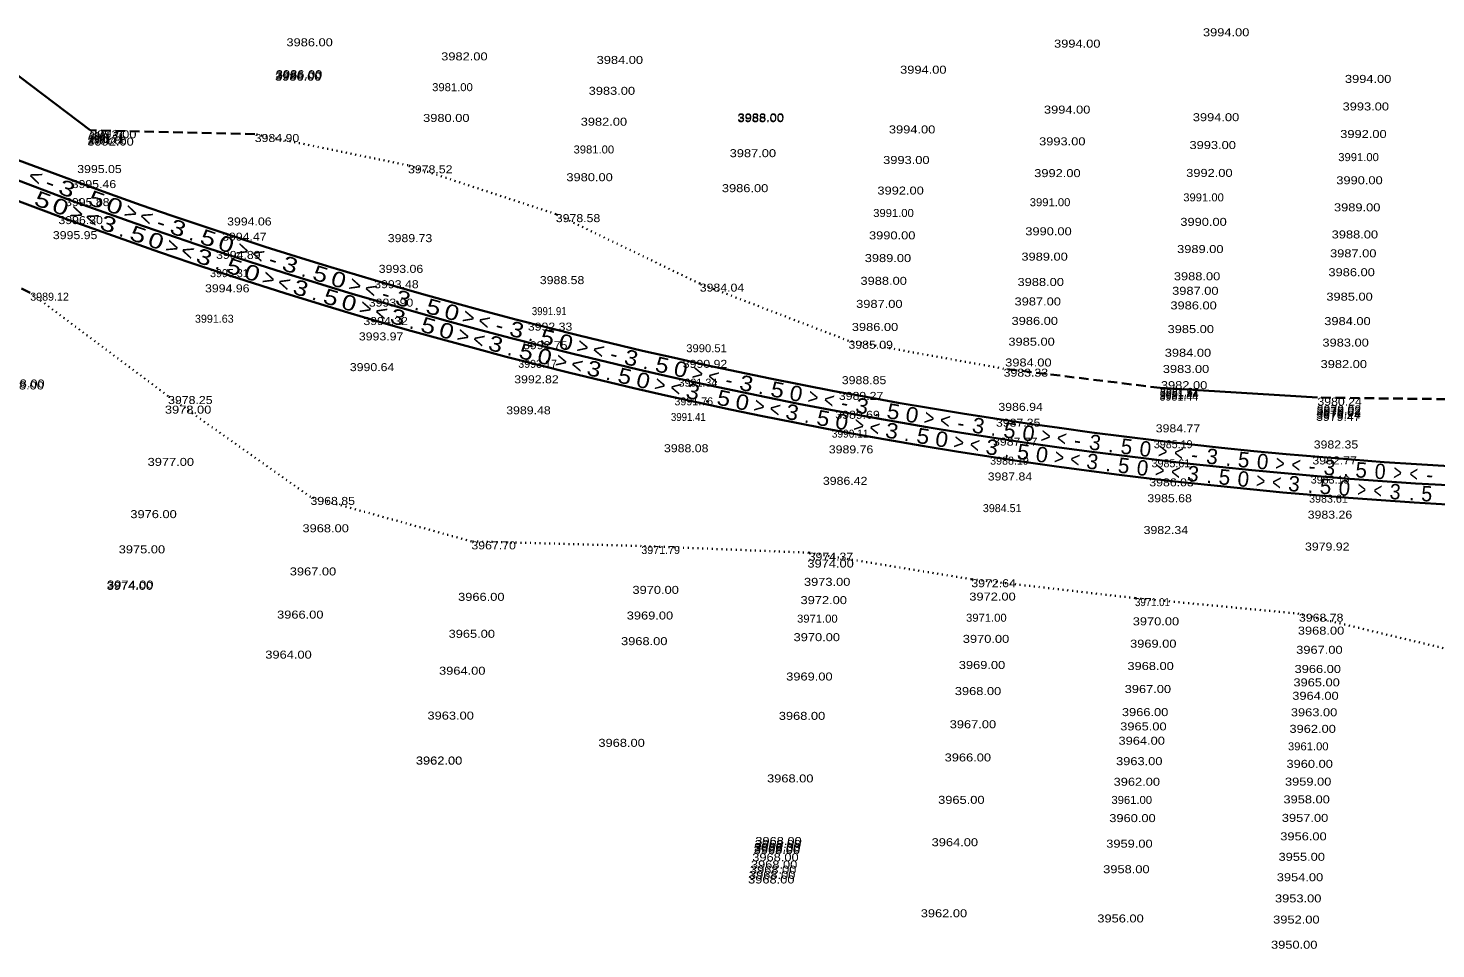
# Model space of a CAD drawing. Extents: x 49942 to 56479, y 47140 to 53283.
# Drawn here: x 51291 to 52171, y 49473 to 50048 of the extents above; entities that cross this region are included whole.
import ezdxf
from ezdxf.enums import TextEntityAlignment as Align

# ---------------------------------------------------------------- set-up
doc = ezdxf.new("R2010")
doc.units = 0
doc.header["$LTSCALE"] = 2
doc.linetypes.add('DOTTED', pattern=[1.5, 0.3, -1.2])
doc.linetypes.add('MEDIUM_DASHED', pattern=[4.5, 3, -1.5])
doc.layers.add('29', color=7, linetype='Continuous')
doc.layers.add('59', color=7, linetype='Continuous', lineweight=35)
doc.layers.add('63', color=7, linetype='Continuous', lineweight=35)

msp = doc.modelspace()

# ---------------------------------------------------------------- linework, layer by layer
at = {"layer": '59'}
for p, q in [((51329.711, 49984.424), (51248.45, 50045.982)), ((52096.806, 49817.413), (51998.49, 49823.498))]:
    msp.add_line(p, q, dxfattribs=at)
at = {"layer": '59', "linetype": 'MEDIUM_DASHED'}
for p, q in [((51432.659, 49982.089), (51329.711, 49984.424)), ((51292.327, 49882.958), (51199.974, 49926.861)), ((51998.49, 49823.498), (51900.7, 49835.484)), ((52195.222, 49816.237), (52096.806, 49817.413))]:
    msp.add_line(p, q, dxfattribs=at)
at = {"layer": '59', "linetype": 'DOTTED'}
for p, q in [((51528.445, 49962.551), (51432.659, 49982.089)), ((51620.827, 49932.041), (51528.445, 49962.551)), ((51710.779, 49888.632), (51620.827, 49932.041)), ((51803.733, 49852.933), (51710.779, 49888.632)), ((51378.49, 49818.374), (51292.327, 49882.958)), ((51900.7, 49835.484), (51803.733, 49852.933)), ((51467.508, 49755.369), (51378.49, 49818.374)), ((51568.059, 49727.587), (51467.508, 49755.369)), ((51674.271, 49724.686), (51568.059, 49727.587)), ((51778.869, 49720.528), (51674.271, 49724.686)), ((51880.529, 49703.937), (51778.869, 49720.528)), ((51982.829, 49692.148), (51880.529, 49703.937)), ((52085.276, 49682.412), (51982.829, 49692.148)), ((52187.039, 49658.165), (52085.276, 49682.412))]:
    msp.add_line(p, q, dxfattribs=at)
at = {"layer": '63'}
for radius in [2975.18, 2987.18, 2987.18, 2999.18]:
    msp.add_arc((52346.841, 52745.042), radius, 246.32672, 271.49967, dxfattribs=at)

# ---------------------------------------------------------------- texts
at = {"layer": '29'}
for s, width, p in [('3994.00', 1.2, (52025.278, 50043.161)), ('3986.00', 1.2, (51452.451, 50036.909)), ('3994.00', 1.2, (51932.224, 50036.07)), ('3982.00', 1.2, (51549.192, 50028.091)), ('3984.00', 1.2, (51646.339, 50025.89)), ('3986.00', 1.2, (51445.341, 50015.42)), ('3986.00', 1.2, (51445.601, 50016.203)), ('3986.00', 1.2, (51445.86, 50016.986)), ('3994.00', 1.2, (51836.006, 50019.792)), ('3994.00', 1.2, (52114.025, 50014.035)), ('3981.00', 1.05, (51543.539, 50008.868)), ('3983.00', 1.2, (51641.358, 50006.591)), ('3994.00', 1.2, (51925.905, 49994.86)), ('3993.00', 1.2, (52112.555, 49996.82)), ('3980.00', 1.2, (51537.885, 49989.645)), ('3982.00', 1.2, (51636.377, 49987.293)), ('3988.00', 1.2, (51734.349, 49989.482)), ('3988.00', 1.2, (51734.387, 49989.651)), ('3988.00', 1.2, (51734.425, 49989.82)), ('3988.00', 1.2, (51734.449, 49989.93)), ('3988.00', 1.2, (51734.473, 49990.039)), ('3994.00', 1.2, (52018.951, 49990.102)), ('3991.71', 0.9, (51328.969, 49977.41)), ('3991.71', 0.9, (51329.315, 49978.348)), ('3992.00', 1.2, (51329.711, 49979.424)), ('3984.90', 1.15, (51432.659, 49977.089)), ('3994.00', 1.2, (51828.998, 49982.471)), ('3992.00', 1.2, (52111.085, 49979.605)), ('3992.00', 1.2, (51328.029, 49974.858)), ('3991.71', 0.9, (51328.623, 49976.472)), ('3981.00', 1.05, (51631.902, 49969.953)), ('3993.00', 1.2, (51922.862, 49975.016)), ('3993.00', 1.2, (52016.876, 49972.7)), ('3987.00', 1.2, (51729.482, 49967.623)), ('3993.00', 1.2, (51825.411, 49963.369)), ('3991.00', 1.05, (52109.851, 49965.153)), ('3995.05', 1.15, (51321.709, 49957.705)), ('3978.52', 1.15, (51528.445, 49957.551)), ('3980.00', 1.2, (51627.427, 49952.613)), ('3992.00', 1.2, (51919.819, 49955.172)), ('3992.00', 1.2, (52014.801, 49955.297)), ('3990.00', 1.2, (52108.617, 49950.701)), ('3995.46', 1.15, (51318.252, 49948.322)), ('3986.00', 1.2, (51724.615, 49945.765)), ('3992.00', 1.2, (51821.824, 49944.268)), ('3995.88', 1.15, (51314.103, 49937.062)), ('3991.00', 1.05, (51917.033, 49936.999)), ('3991.00', 1.05, (52012.979, 49940.012)), ('3989.00', 1.2, (52107.171, 49933.776)), ('3996.30', 1.15, (51309.954, 49925.801)), ('3994.06', 1.15, (51415.408, 49924.953)), ('3978.58', 1.15, (51620.827, 49927.041)), ('3991.00', 1.05, (51819.196, 49930.275)), ('3990.00', 1.2, (52011.156, 49924.726)), ('3995.95', 1.15, (51306.497, 49916.418)), ('3994.47', 1.15, (51412.267, 49915.459)), ('3990.00', 1.2, (51816.568, 49916.282)), ('3990.00', 1.2, (51914.246, 49918.826)), ('3988.00', 1.2, (52105.726, 49916.851)), ('3989.73', 1.15, (51515.795, 49914.542)), ('3989.00', 1.2, (52009.129, 49907.723)), ('3994.89', 1.15, (51408.498, 49904.066)), ('3989.00', 1.2, (51813.901, 49902.079)), ('3989.00', 1.2, (51911.818, 49902.991)), ('3987.00', 1.2, (52104.718, 49905.051)), ('3993.06', 1.15, (51510.152, 49895.355)), ('3988.00', 1.2, (52007.101, 49890.719)), ('3986.00', 1.2, (52103.71, 49893.252)), ('3994.96', 1.15, (51401.587, 49883.18)), ('3993.48', 1.15, (51507.33, 49885.761)), ('3988.58', 1.15, (51610.831, 49888.31)), ('3984.04', 1.15, (51710.779, 49883.632)), ('3988.00', 1.2, (51811.234, 49887.877)), ('3988.00', 1.2, (51909.39, 49887.155)), ('3987.00', 1.2, (52006.018, 49881.636)), ('3993.90', 1.15, (51503.944, 49874.249)), ('3987.00', 1.2, (51808.528, 49873.466)), ('3987.00', 1.2, (51907.525, 49874.993)), ('3986.00', 1.2, (52004.93, 49872.506)), ('3985.00', 1.2, (52102.406, 49877.982)), ('3994.32', 1.15, (51500.558, 49862.736)), ('3991.91', 0.9, (51605.832, 49868.944)), ('3986.00', 1.2, (51905.66, 49862.831)), ('3984.00', 1.2, (52101.102, 49862.713)), ('3992.33', 1.15, (51603.333, 49859.262)), ('3986.00', 1.2, (51805.822, 49859.056)), ('3985.00', 1.2, (52003.167, 49857.719)), ('3993.97', 1.15, (51497.736, 49853.143)), ('3992.75', 1.15, (51600.335, 49847.642)), ('3990.51', 1.05, (51702.344, 49845.751)), ('3985.09', 1.15, (51803.733, 49847.933)), ('3985.00', 1.2, (51903.668, 49849.842)), ('3983.00', 1.2, (52099.955, 49849.287)), ('3990.92', 1.15, (51700.17, 49835.99)), ('3984.00', 1.2, (51901.677, 49836.854)), ('3984.00', 1.2, (52001.404, 49842.932)), ('3982.00', 1.2, (52098.809, 49835.861)), ('3990.64', 1.15, (51492.093, 49833.955)), ('3983.33', 1.15, (51900.7, 49830.484)), ('3983.00', 1.2, (52000.197, 49832.814)), ('3988.00', 1.2, (51271.892, 49822.495)), ('3988.00', 1.2, (51272.345, 49823.726)), ('3992.82', 1.15, (51594.837, 49826.34)), ('3988.85', 1.15, (51799.577, 49825.801)), ('3982.00', 1.2, (51998.99, 49822.689)), ('3978.25', 1.15, (51378.49, 49813.374)), ('3989.27', 1.15, (51797.731, 49815.973)), ('3980.24', 1.15, (52096.806, 49812.413)), ('3978.00', 1.2, (51376.514, 49807.402)), ('3989.48', 1.15, (51589.839, 49806.975)), ('3991.41', 0.9, (51692.78, 49802.803)), ('3989.69', 1.15, (51795.517, 49804.18)), ('3986.94', 1.15, (51897.424, 49809.117)), ('3979.47', 1.15, (52095.99, 49802.863)), ('3979.24', 1.15, (52096.105, 49804.204)), ('3979.02', 1.15, (52096.219, 49805.544)), ('3979.02', 1.15, (52096.305, 49806.541)), ('3979.02', 1.15, (52096.39, 49807.537)), ('3990.11', 0.95, (51793.302, 49792.386)), ('3987.35', 1.15, (51895.908, 49799.233)), ('3984.77', 1.15, (51995.774, 49795.717)), ('3988.08', 1.15, (51688.433, 49783.281)), ('3987.77', 1.15, (51894.089, 49787.372)), ('3982.35', 1.15, (52094.518, 49785.617)), ('3977.00', 1.2, (51365.71, 49774.748)), ('3989.76', 1.15, (51791.456, 49782.557)), ('3982.77', 1.15, (52093.666, 49775.653)), ('3987.84', 1.15, (51890.755, 49765.626)), ('3986.42', 1.15, (51787.765, 49762.901)), ('3986.03', 1.15, (51991.748, 49761.957)), ('3968.85', 1.15, (51467.508, 49750.368)), ('3985.68', 1.15, (51990.564, 49752.027)), ('3976.00', 1.2, (51354.905, 49742.093)), ('3983.26', 1.15, (52090.773, 49741.776)), ('3968.00', 1.2, (51462.479, 49733.27)), ('3982.34', 1.15, (51988.196, 49732.168)), ('3967.70', 1.15, (51568.059, 49722.587)), ('3979.92', 1.15, (52089.071, 49721.849)), ('3975.00', 1.2, (51347.632, 49720.11)), ('3974.37', 1.15, (51778.869, 49715.528)), ('3967.00', 1.2, (51454.547, 49706.301)), ('3974.00', 1.2, (51778.061, 49711.226)), ('3974.00', 1.2, (51340.086, 49697.304)), ('3974.00', 1.2, (51340.358, 49698.127)), ('3973.00', 1.2, (51775.916, 49699.805)), ('3972.64', 1.15, (51880.529, 49698.937)), ('3966.00', 1.2, (51559.758, 49690.426)), ('3970.00', 1.2, (51668.725, 49694.78)), ('3972.00', 1.2, (51773.772, 49688.385)), ('3972.00', 1.2, (51879.249, 49690.588)), ('3971.01', 0.9, (51982.829, 49687.148)), ('3966.00', 1.2, (51446.614, 49679.332)), ('3969.00', 1.2, (51665.158, 49678.762)), ('3971.00', 1.05, (51771.598, 49676.81)), ('3971.00', 1.05, (51877.224, 49677.381)), ('3970.00', 1.2, (51981.397, 49675.139)), ('3968.00', 1.2, (52084.586, 49669.331)), ('3968.78', 1.15, (52085.276, 49677.412)), ('3965.00', 1.2, (51553.802, 49667.349)), ('3968.00', 1.2, (51661.592, 49662.743)), ('3970.00', 1.2, (51769.424, 49665.235)), ('3970.00', 1.2, (51875.198, 49664.173)), ('3969.00', 1.2, (51979.731, 49661.173)), ('3964.00', 1.2, (51439.261, 49654.331)), ('3967.00', 1.2, (52083.563, 49657.349)), ('3964.00', 1.2, (51547.846, 49644.271)), ('3969.00', 1.2, (51872.697, 49647.86)), ('3968.00', 1.2, (51978.066, 49647.207)), ('3966.00', 1.2, (52082.539, 49645.366)), ('3969.00', 1.2, (51764.808, 49640.651)), ('3965.00', 1.2, (52081.824, 49636.987)), ('3968.00', 1.2, (51870.196, 49631.548)), ('3967.00', 1.2, (51976.354, 49632.844)), ('3964.00', 1.2, (52081.108, 49628.609)), ('3963.00', 1.2, (51540.609, 49616.233)), ('3968.00', 1.2, (51760.191, 49616.067)), ('3966.00', 1.2, (51974.633, 49618.417)), ('3963.00', 1.2, (52080.226, 49618.284)), ('3967.00', 1.2, (51867.017, 49610.816)), ('3965.00', 1.2, (51973.567, 49609.474)), ('3962.00', 1.2, (52079.345, 49607.959)), ('3968.00', 1.2, (51647.444, 49599.208)), ('3964.00', 1.2, (51972.501, 49600.53)), ('3966.00', 1.2, (51863.838, 49590.085)), ('3961.00', 1.05, (52078.411, 49597.025)), ('3962.00', 1.2, (51533.34, 49588.068)), ('3962.00', 1.2, (51533.371, 49588.187)), ('3963.00', 1.2, (51970.978, 49587.76)), ('3960.00', 1.2, (52077.477, 49586.091)), ('3968.00', 1.2, (51752.85, 49576.976)), ('3962.00', 1.2, (51969.445, 49574.903)), ('3959.00', 1.2, (52076.529, 49574.99)), ('3965.00', 1.2, (51859.777, 49563.601)), ('3961.00', 1.05, (51968.09, 49563.542)), ('3958.00', 1.2, (52075.581, 49563.888)), ('3960.00', 1.2, (51966.736, 49552.181)), ('3957.00', 1.2, (52074.594, 49552.333)), ('3968.00', 1.2, (51745.509, 49537.885)), ('3964.00', 1.2, (51855.716, 49537.117)), ('3956.00', 1.2, (52073.607, 49540.778)), ('3968.00', 1.2, (51744.454, 49532.264)), ('3968.00', 1.2, (51744.633, 49533.218)), ('3968.00', 1.2, (51744.812, 49534.171)), ('3968.00', 1.2, (51745.161, 49536.028)), ('3959.00', 1.2, (51964.832, 49536.215)), ('3955.00', 1.2, (52072.516, 49528.008)), ('3968.00', 1.2, (51742.142, 49519.953)), ('3968.00', 1.2, (51742.751, 49523.196)), ('3968.00', 1.2, (51743.602, 49527.73)), ('3958.00', 1.2, (51962.928, 49520.249)), ('3968.00', 1.2, (51740.99, 49513.821)), ('3968.00', 1.2, (51741.533, 49516.709)), ('3954.00', 1.2, (52071.426, 49515.238)), ('3953.00', 1.2, (52070.297, 49502.016)), ('3962.00', 1.2, (51848.91, 49492.727)), ('3956.00', 1.2, (51959.261, 49489.492)), ('3952.00', 1.2, (52069.167, 49488.794)), ('3950.00', 1.2, (52067.825, 49473.077))]:
    msp.add_text(s, height=5, dxfattribs=dict(at, width=width)).set_placement(p)
for s, p in [('3991.86', (51328.326, 49975.665)), ('3995.31', (51404.728, 49892.673)), ('3989.12', (51292.326, 49877.958)), ('3991.63', (51395.304, 49864.192)), ('3993.17', (51597.336, 49836.023)), ('3991.34', (51697.562, 49824.277)), ('3981.67', (51998.49, 49818.498)), ('3991.76', (51694.953, 49812.564)), ('3981.44', (51998.142, 49815.577)), ('3981.44', (51998.26, 49816.57)), ('3981.44', (51998.379, 49817.563)), ('3985.19', (51994.59, 49785.788)), ('3988.19', (51892.27, 49775.51)), ('3985.61', (51993.169, 49773.872)), ('3983.19', (52092.645, 49763.697)), ('3983.61', (52091.624, 49751.74)), ('3984.51', (51887.724, 49745.857)), ('3971.79', (51674.271, 49719.686))]:
    msp.add_text(s, height=5, dxfattribs=at).set_placement(p)
at = {"layer": '63'}
for s, rotation, width, p in [('<', 339.319, 1.1, (51293.978, 49950.842)), ('5', 339.499, 1.35, (51298.559, 49936.309)), ('-', 339.512, 1.25, (51303.403, 49947.309)), ('3', 339.723, 1.35, (51313.683, 49943.497)), ('5', 340.105, 1.35, (51332.357, 49936.682)), ('0', 339.725, 1.35, (51309.638, 49932.199)), ('0', 340.333, 1.35, (51343.523, 49932.673)), ('>', 340.544, 1.05, (51353.856, 49929.007)), ('>', 339.934, 1.1, (51319.89, 49928.439)), ('<', 340.126, 1.1, (51329.315, 49925.021)), ('3', 340.335, 1.35, (51339.594, 49921.334)), ('<', 340.737, 1.05, (51363.355, 49925.676)), ('5', 340.714, 1.35, (51358.264, 49914.744)), ('0', 340.941, 1.3, (51369.427, 49910.869)), ('-', 340.931, 1.2, (51372.864, 49922.376)), ('3', 341.142, 1.3, (51383.236, 49918.82)), ('5', 341.524, 1.3, (51402.073, 49912.467)), ('>', 341.15, 1.05, (51379.758, 49907.326)), ('0', 341.752, 1.3, (51413.335, 49908.736)), ('<', 341.342, 1.05, (51389.252, 49904.108)), ('3', 341.551, 1.3, (51399.608, 49900.64)), ('5', 341.93, 1.3, (51418.414, 49894.446)), ('-', 342.35, 1.2, (51442.923, 49899.167)), ('3', 342.56, 1.3, (51453.38, 49895.868)), ('0', 342.156, 1.3, (51429.657, 49890.809)), ('5', 342.942, 1.25, (51472.368, 49889.983)), ('0', 343.171, 1.25, (51483.719, 49886.531)), ('3', 342.766, 1.25, (51460.048, 49881.221)), ('5', 343.145, 1.25, (51478.981, 49875.427)), ('0', 343.372, 1.25, (51490.299, 49872.028)), ('-', 343.768, 1.15, (51513.535, 49877.696)), ('3', 343.979, 1.25, (51524.071, 49874.656)), ('5', 344.361, 1.25, (51543.2, 49869.242)), ('3', 343.982, 1.25, (51520.887, 49863.086)), ('5', 344.361, 1.25, (51539.939, 49857.693)), ('0', 344.589, 1.25, (51554.633, 49866.071)), ('<', 344.994, 0.95, (51574.93, 49860.562)), ('0', 344.587, 1.25, (51551.326, 49854.535)), ('-', 345.187, 1.1, (51584.659, 49857.976)), ('3', 345.398, 1.2, (51595.267, 49855.198)), ('5', 345.78, 1.2, (51614.524, 49850.258)), ('<', 344.988, 0.95, (51571.542, 49849.046)), ('3', 345.197, 1.2, (51582.098, 49846.242)), ('5', 345.576, 1.2, (51601.26, 49841.255)), ('0', 346.008, 1.2, (51626.032, 49847.371)), ('>', 346.219, 0.95, (51636.678, 49844.742)), ('0', 345.802, 1.2, (51612.712, 49838.338)), ('>', 346.011, 0.95, (51623.306, 49835.682)), ('<', 346.412, 0.95, (51646.46, 49842.364)), ('-', 346.606, 1.05, (51656.25, 49840.02)), ('3', 346.817, 1.15, (51666.923, 49837.504)), ('5', 347.199, 1.15, (51686.297, 49833.042)), ('<', 346.203, 0.95, (51633.04, 49833.279)), ('3', 346.412, 1.2, (51643.652, 49830.698)), ('5', 346.792, 1.15, (51662.916, 49826.118)), ('0', 347.018, 1.15, (51674.428, 49823.444)), ('0', 347.427, 1.15, (51697.874, 49830.44)), ('>', 347.637, 0.9, (51708.582, 49828.075)), ('<', 347.831, 0.9, (51718.419, 49825.94)), ('>', 347.227, 0.9, (51685.076, 49821.013)), ('<', 347.419, 0.9, (51694.858, 49818.816)), ('3', 347.628, 1.15, (51705.524, 49816.461)), ('3', 348.235, 1.15, (51738.997, 49821.587)), ('5', 348.617, 1.15, (51758.475, 49817.605)), ('0', 348.845, 1.1, (51770.113, 49815.29)), ('5', 348.007, 1.15, (51724.881, 49812.29)), ('0', 348.233, 1.15, (51736.446, 49809.86)), ('>', 348.442, 0.9, (51747.143, 49807.655)), ('>', 349.056, 0.85, (51780.876, 49813.19)), ('<', 349.25, 0.85, (51790.764, 49811.299)), ('3', 349.654, 1.1, (51811.443, 49807.456)), ('<', 348.634, 0.9, (51756.971, 49805.666)), ('3', 348.843, 1.1, (51767.683, 49803.538)), ('5', 349.222, 1.1, (51787.124, 49799.777)), ('0', 349.449, 1.1, (51798.739, 49797.593)), ('.', 349.845, 0.9, (51821.225, 49805.688)), ('5', 350.036, 1.1, (51831.014, 49803.956)), ('0', 350.264, 1.1, (51842.705, 49801.93)), ('>', 350.475, 0.85, (51853.518, 49800.097)), ('<', 350.668, 0.85, (51863.449, 49798.45)), ('.', 349.033, 0.95, (51777.4, 49801.639)), ('>', 349.658, 0.85, (51809.481, 49795.615)), ('<', 349.85, 0.85, (51819.348, 49793.834)), ('3', 350.059, 1.1, (51830.104, 49791.933)), ('5', 350.438, 1.1, (51849.62, 49788.584)), ('3', 351.073, 1.05, (51884.217, 49795.119)), ('5', 351.455, 1.05, (51903.869, 49792.105)), ('0', 351.683, 1.05, (51915.607, 49790.367)), ('>', 351.894, 0.8, (51926.461, 49788.803)), ('.', 350.248, 0.9, (51839.859, 49790.24)), ('0', 350.664, 1.1, (51861.279, 49786.647)), ('>', 350.873, 0.85, (51872.06, 49784.897)), ('<', 351.065, 0.8, (51881.963, 49783.325)), ('3', 351.274, 1.05, (51892.757, 49781.652)), ('.', 351.264, 0.85, (51894.04, 49793.594)), ('5', 351.653, 1.05, (51912.34, 49778.718)), ('<', 352.087, 0.8, (51936.431, 49787.402)), ('.', 351.464, 0.85, (51902.546, 49780.167)), ('0', 351.879, 1.05, (51924.037, 49777.028)), ('>', 352.089, 0.8, (51934.853, 49775.506)), ('<', 352.281, 0.8, (51944.787, 49774.145)), ('>', 353.312, 0.75, (51999.663, 49779.315)), ('<', 353.506, 0.75, (52009.664, 49778.161)), ('>', 354.731, 0.75, (52073.078, 49771.639)), ('>', 353.304, 0.75, (51997.832, 49767.447)), ('<', 353.496, 0.75, (52007.792, 49766.297)), ('<', 354.925, 0.75, (52083.104, 49770.733)), ('0', 355.939, 0.95, (52135.719, 49766.537)), ('>', 356.15, 0.7, (52146.66, 49765.781)), ('<', 356.343, 0.7, (52156.706, 49765.123)), ('>', 354.519, 0.75, (52060.967, 49760.724)), ('<', 354.711, 0.75, (52070.95, 49759.785)), ('>', 355.735, 0.7, (52124.231, 49755.339)), ('<', 355.927, 0.7, (52134.232, 49754.612)), ('3', 356.136, 0.95, (52145.129, 49753.858)), ('5', 356.515, 0.95, (52164.891, 49752.591))]:
    msp.add_text(s, height=9.6, rotation=rotation, dxfattribs=dict(at, width=width)).set_placement(p, align=Align.CENTER)
for s, rotation, p in [('.', 339.914, (51323.014, 49940.072)), ('.', 340.525, (51348.923, 49918.021)), ('.', 341.333, (51392.648, 49915.626)), ('>', 341.963, (51423.756, 49905.326)), ('<', 342.156, (51433.334, 49902.231)), ('.', 341.74, (51409.005, 49897.526)), ('>', 342.365, (51440.06, 49887.486)), ('.', 342.751, (51462.868, 49892.908)), ('<', 342.557, (51449.621, 49884.469)), ('>', 343.381, (51494.222, 49883.379)), ('<', 343.575, (51503.874, 49880.521)), ('.', 342.956, (51469.509, 49878.306)), ('>', 343.581, (51500.77, 49868.926)), ('<', 343.773, (51510.393, 49866.113)), ('.', 344.17, (51533.63, 49871.931)), ('>', 344.8, (51565.211, 49863.181)), ('.', 344.171, (51530.408, 49860.372)), ('>', 344.796, (51561.862, 49851.655)), ('.', 345.589, (51604.891, 49852.71)), ('.', 345.387, (51591.674, 49843.731)), ('.', 347.008, (51676.606, 49835.255)), ('.', 346.602, (51653.28, 49828.39)), ('-', 348.024, (51728.264, 49823.838)), ('.', 347.817, (51715.198, 49814.358)), ('.', 348.426, (51748.732, 49819.578)), ('-', 349.443, (51800.658, 49809.441)), ('-', 350.862, (51873.386, 49796.837)), ('-', 352.281, (51946.405, 49786.035)), ('3', 352.491, (51957.275, 49784.586)), ('5', 352.874, (51976.996, 49782.057)), ('0', 353.102, (51988.773, 49780.611)), ('3', 352.49, (51955.614, 49772.701)), ('.', 352.682, (51967.525, 49783.253)), ('5', 352.869, (51975.255, 49770.181)), ('-', 353.699, (52019.669, 49777.041)), ('3', 353.91, (52030.572, 49775.861)), ('5', 354.292, (52050.349, 49773.821)), ('0', 354.52, (52062.159, 49772.666)), ('.', 352.679, (51965.824, 49771.373)), ('0', 353.095, (51986.986, 49768.74)), ('3', 353.705, (52018.647, 49765.082)), ('5', 354.084, (52038.338, 49762.979)), ('.', 354.101, (52040.972, 49774.769)), ('0', 354.31, (52050.096, 49761.787)), ('-', 355.118, (52093.133, 49769.861)), ('3', 355.329, (52104.062, 49768.95)), ('5', 355.711, (52123.884, 49767.4)), ('.', 353.895, (52028.986, 49763.96)), ('3', 354.92, (52081.828, 49758.8)), ('5', 355.3, (52101.559, 49757.115)), ('0', 355.526, (52113.34, 49756.171)), ('.', 355.52, (52114.606, 49768.107)), ('-', 356.537, (52166.754, 49764.499)), ('.', 355.11, (52092.291, 49757.888)), ('.', 356.325, (52155.71, 49753.161))]:
    msp.add_text(s, height=9.6, rotation=rotation, dxfattribs=at).set_placement(p, align=Align.CENTER)

doc.saveas('drawing.dxf')
